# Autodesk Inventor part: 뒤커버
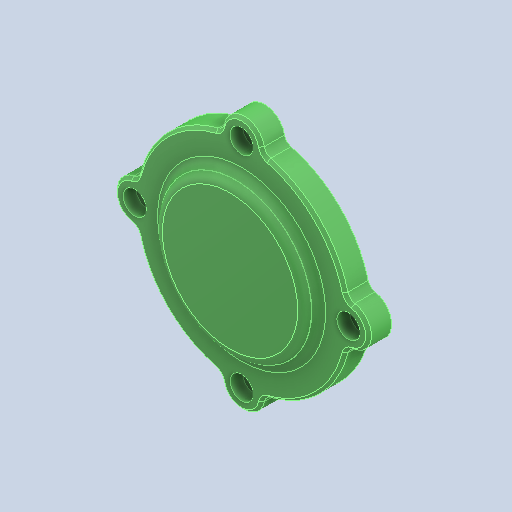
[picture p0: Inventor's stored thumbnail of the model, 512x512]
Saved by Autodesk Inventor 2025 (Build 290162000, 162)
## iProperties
Created: 2024-08
Part Number: 뒤커버
Material: 알루미늄 6061
Document SubType Name: Modeling
Designer: SAMSUNG
Density: 2.71 g/cm^3
Appearance: 기본값
Company: 한국ATC센터
Author: jhkim
Sending System: Autodesk Inventor 2025
Preprocessor: ST-DEVELOPER v20
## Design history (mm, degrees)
feature "솔리드1"
node "솔리드2"
